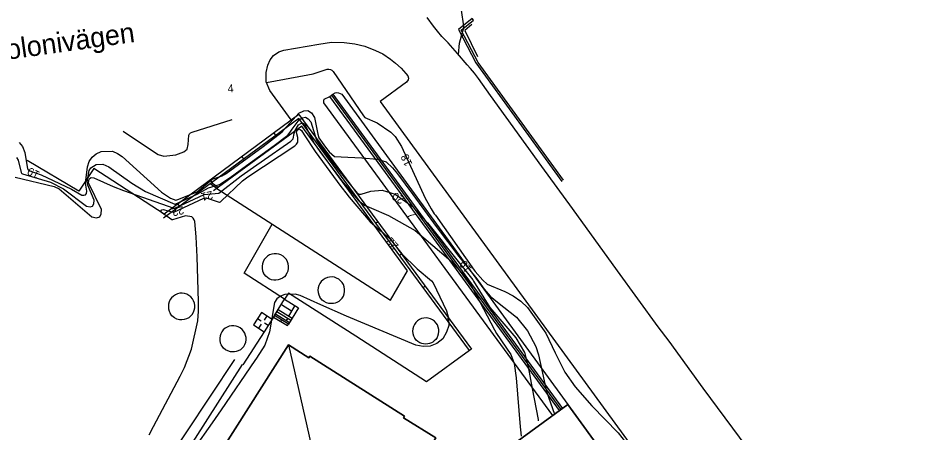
# Model space of a CAD drawing. Extents: x 67169 to 69652, y 20189 to 22818.
# Drawn here: x 69486.1 to 69599.6, y 21189.9 to 21241.7 of the extents above; entities that cross this region are included whole.
import ezdxf

# ---------------------------------------------------------------- set-up
doc = ezdxf.new("R2010")
doc.units = 0
for name, color, linetype in [('BYGGNAD_HUSLIV', 7, 'Continuous'), ('BYGGNAD_HUSLIV 11', 7, 'Continuous'), ('BYGGNADSDETALJER', 7, 'Continuous'), ('BYGGNADSDETALJER 19', 7, 'Continuous'), ('BYGGNADSSYMBOLER', 7, 'Continuous'), ('BYGGNADSSYMBOLER 30', 7, 'Continuous'), ('GATUNAMN', 7, 'Continuous'), ('HOJDKURVOR_2014', 7, 'Continuous'), ('HOJDKURVOR_2014 5M', 7, 'Continuous'), ('HOJDKURVOR_TEXTER_2014', 7, 'Continuous'), ('Instruktioner', 7, 'Continuous'), ('MUR_STAKET', 7, 'Continuous'), ('MUR_STAKET_SYMBOL', 7, 'Continuous'), ('Std_Ritningsstämpel', 7, 'Continuous'), ('VAGAR 121', 7, 'Continuous')]:
    doc.layers.add(name, color=color, linetype=linetype)

msp = doc.modelspace()

# ---------------------------------------------------------------- linework, layer by layer
at = {"layer": 'BYGGNAD_HUSLIV'}
for points in [[(69519.9, 21200.89), (69522.45, 21199.27), (69522.57, 21199.47), (69534.4, 21191.97), (69534.28, 21191.77), (69538.28, 21189.24), (69526.74, 21170.81), (69522.74, 21173.34), (69522.62, 21173.14), (69510.68, 21180.69), (69510.8, 21180.88), (69508.25, 21182.5), (69519.9, 21200.89)], [(69544.44, 21185.88), (69554.8, 21193.43), (69589.88, 21145.14), (69579.54, 21137.63), (69577.94, 21140.02), (69577.23, 21139.47), (69548.93, 21157.38), (69548.85, 21158.64), (69544.93, 21161.12), (69543.76, 21160.66), (69534.77, 21166.35), (69545.88, 21183.92), (69544.44, 21185.88)]]:
    msp.add_lwpolyline(points, dxfattribs=at)
at = {"layer": 'BYGGNAD_HUSLIV 11'}
for points in [[(69519.9, 21200.89), (69522.45, 21199.27), (69522.57, 21199.47), (69534.4, 21191.97), (69534.28, 21191.77), (69538.28, 21189.24), (69526.74, 21170.81), (69522.74, 21173.34), (69522.62, 21173.14), (69510.68, 21180.69), (69510.8, 21180.88), (69508.25, 21182.5), (69519.9, 21200.89)], [(69544.44, 21185.88), (69554.8, 21193.43), (69589.88, 21145.14), (69579.54, 21137.63), (69577.94, 21140.02), (69577.23, 21139.47), (69548.93, 21157.38), (69548.85, 21158.64), (69544.93, 21161.12), (69543.76, 21160.66), (69534.77, 21166.35), (69545.88, 21183.92), (69544.44, 21185.88)]]:
    msp.add_lwpolyline(points, dxfattribs=at)
at = {"layer": 'BYGGNADSDETALJER'}
for p, q in [((69520.7, 21205.77), (69519.89, 21204.47)), ((69518.28, 21204.74), (69520.01, 21203.66)), ((69518.45, 21205.03), (69520.2, 21203.97)), ((69518.6, 21205.27), (69520.34, 21204.2)), ((69519.81, 21204.2), (69519.62, 21203.9))]:
    msp.add_line(p, q, dxfattribs=at)
for points in [[(69519.57, 21209.6), (69519.38, 21209.38), (69519.15, 21209.2), (69518.87, 21209.06), (69518.6, 21208.98), (69518.33, 21208.95), (69518.05, 21208.95), (69517.76, 21209.01), (69517.49, 21209.13), (69517.27, 21209.27), (69517.06, 21209.45), (69516.88, 21209.67), (69516.77, 21209.84)], [(69519.4, 21206.58), (69521.16, 21205.49), (69519.88, 21203.46), (69518.16, 21204.55), (69519.4, 21206.58)], [(69526.58, 21206.7), (69526.38, 21206.48), (69526.17, 21206.31), (69525.95, 21206.17), (69525.74, 21206.1), (69525.5, 21206.05), (69525.22, 21206.03), (69524.95, 21206.05), (69524.64, 21206.14), (69524.37, 21206.28), (69524.09, 21206.47), (69523.92, 21206.66), (69523.79, 21206.85)], [(69507.86, 21204.68), (69507.65, 21204.45), (69507.43, 21204.26), (69507.17, 21204.12), (69506.87, 21204.03), (69506.57, 21203.99), (69506.26, 21204.01), (69505.96, 21204.1), (69505.64, 21204.24), (69505.33, 21204.5), (69505.13, 21204.83)], [(69514.31, 21200.68), (69514.11, 21200.45), (69513.88, 21200.25), (69513.62, 21200.12), (69513.37, 21200.03), (69513.14, 21199.99), (69512.87, 21199.99), (69512.63, 21200), (69512.33, 21200.11), (69512.04, 21200.25), (69511.77, 21200.47), (69511.59, 21200.69), (69511.48, 21200.86)], [(69538.47, 21201.8), (69538.3, 21201.56), (69538.11, 21201.37), (69537.93, 21201.23), (69537.75, 21201.13), (69537.5, 21201.04), (69537.29, 21200.99), (69537.03, 21200.96), (69536.77, 21200.99), (69536.54, 21201.03), (69536.29, 21201.14), (69536.06, 21201.28), (69535.85, 21201.45), (69535.67, 21201.69), (69535.64, 21201.76)]]:
    msp.add_lwpolyline(points, dxfattribs=at)
for centre, radius, start, end in [((69518.25, 21210.6), 1.66, 322.7319, 207.3253), ((69525.24, 21207.69), 1.67, 323.7038, 210.1769), ((69506.54, 21205.68), 1.65, 322.6524, 211.0987), ((69537.04, 21202.6), 1.64, 326.5291, 211.2003), ((69512.95, 21201.62), 1.65, 325.0952, 207.2906)]:
    msp.add_arc(centre, radius, start, end, dxfattribs=at)
at = {"layer": 'BYGGNADSDETALJER 19'}
for p, q in [((69520.7, 21205.77), (69519.89, 21204.47)), ((69518.28, 21204.74), (69520.01, 21203.66)), ((69518.45, 21205.03), (69520.2, 21203.97)), ((69518.6, 21205.27), (69520.34, 21204.2)), ((69519.81, 21204.2), (69519.62, 21203.9))]:
    msp.add_line(p, q, dxfattribs=at)
msp.add_lwpolyline([(69519.4, 21206.58), (69521.16, 21205.49), (69519.88, 21203.46), (69518.16, 21204.55), (69519.4, 21206.58)], dxfattribs=at)
at = {"layer": 'BYGGNADSSYMBOLER'}
for p, q in [((69519, 21205.91), (69520.29, 21205.11)), ((69519, 21205.91), (69519, 21205.91)), ((69519.9, 21200.89), (69526.74, 21170.81))]:
    msp.add_line(p, q, dxfattribs=at)
at = {"layer": 'BYGGNADSSYMBOLER 30'}
msp.add_line((69519.9, 21200.89), (69526.74, 21170.81), dxfattribs=at)
at = {"layer": 'HOJDKURVOR_2014'}
for points in [[(69541.11, 21237.16), (69541.26, 21238.58), (69541.51, 21239.48), (69541.77, 21240.35), (69541.78, 21240.66), (69541.76, 21240.96), (69540.92, 21246.69), (69540.42, 21247.96), (69539.42, 21248.89), (69535.93, 21249.75), (69535.23, 21249.95), (69532.59, 21250.8)], [(69517.15, 21233.66), (69522.33, 21234.59), (69522.98, 21234.75), (69524.71, 21235.33), (69524.94, 21235.33), (69525.14, 21235.29), (69525.32, 21235.18), (69525.48, 21235.02), (69529.26, 21229.49), (69529.45, 21229.28), (69530.99, 21228.59), (69532.66, 21227.44), (69533.2, 21226.92), (69534.02, 21225.64), (69536.98, 21219.2), (69537.28, 21218.6), (69537.72, 21217.85), (69538.1, 21217.26), (69538.24, 21217.07), (69543.09, 21210.2), (69543.22, 21210.02), (69544.17, 21208.94), (69544.69, 21208.47), (69546.91, 21207.53), (69547.95, 21206.99), (69548.91, 21206.34), (69549.75, 21205.54), (69552.03, 21202.32), (69553.22, 21199.89), (69554.41, 21197.47), (69555.69, 21195.62), (69557.77, 21193.25), (69561.07, 21189.9), (69563.38, 21186.98)], [(69486.27, 21226.15), (69486.66, 21225.64), (69486.97, 21224.89), (69487.31, 21222.88), (69487.37, 21222.79), (69487.59, 21222.6), (69488.98, 21222.1), (69492.77, 21220.34), (69494.06, 21219.59), (69494.33, 21219.56), (69494.54, 21219.61), (69494.66, 21219.8), (69494.71, 21220.07), (69494.53, 21221.06), (69494.78, 21223.12), (69495.01, 21223.78), (69495.35, 21224.34), (69495.87, 21224.74), (69496.5, 21225.04), (69497.9, 21225.05), (69498.53, 21224.79), (69499.13, 21224.39), (69504.03, 21219.94), (69505.17, 21219.2), (69505.81, 21218.93), (69506.18, 21219.07), (69506.69, 21219.27), (69508.5, 21219.99), (69510.37, 21221.58), (69511.61, 21221.97), (69511.92, 21222.16), (69512.01, 21222.23), (69512.11, 21222.3), (69516.71, 21225.67), (69519.09, 21227.47), (69519.35, 21227.78), (69521.18, 21229.83), (69521.79, 21230.12), (69522.33, 21230.17), (69522.77, 21229.85), (69523.14, 21229.29), (69523.55, 21227.18), (69523.69, 21226.74), (69524.53, 21225.55), (69524.98, 21224.98), (69525.63, 21224.41), (69527.32, 21224.33), (69529.05, 21224.25), (69531.03, 21224.05), (69532.08, 21223.72), (69532.9, 21223), (69533.49, 21222.22), (69535.41, 21219.65), (69538.36, 21215.64), (69541.19, 21211.92), (69543.4, 21209.14), (69544.32, 21207.85), (69545.09, 21206.95), (69546.01, 21206.2), (69548.38, 21204.34), (69549.75, 21202.61), (69550.78, 21200.66), (69551.14, 21199.62), (69552.13, 21195.04), (69553.12, 21192.2)], [(69485.76, 21221.81), (69490.61, 21220.67), (69491.24, 21220.37), (69495.34, 21216.87), (69495.9, 21216.76), (69496.31, 21216.85), (69496.5, 21217.23), (69496.54, 21217.8), (69494.92, 21221.13), (69494.92, 21221.14), (69495, 21221.56), (69495.05, 21221.65), (69495.24, 21221.76), (69495.59, 21221.75), (69497.98, 21220.65), (69499.28, 21220.16), (69505.58, 21217.93), (69505.68, 21217.94), (69509.35, 21219.66), (69511.19, 21219.81), (69514, 21222), (69515.93, 21223.37), (69516.47, 21223.75), (69520.19, 21226.32), (69520.46, 21226.63), (69520.59, 21227.26), (69520.71, 21227.65), (69521.15, 21228.34), (69521.42, 21228.51), (69521.67, 21228.58), (69521.91, 21228.46), (69523.14, 21225.99), (69523.8, 21225.02), (69526.5, 21221.42), (69528.59, 21218.94), (69529.37, 21218.34), (69530.26, 21217.94), (69532.39, 21217.05), (69535.72, 21215.14), (69536.81, 21214.23), (69539.87, 21211.61), (69540.93, 21210.54), (69542.41, 21208.84), (69542.45, 21208.79), (69545.64, 21202.73), (69545.88, 21202.29), (69547.65, 21199.69), (69548.1, 21198.54), (69548.34, 21196.77), (69548.84, 21190.63), (69548.88, 21190.24), (69548.95, 21189.47)], [(69499.23, 21227.55), (69500.05, 21227.04), (69503.62, 21224.64), (69504.33, 21224.43), (69505.83, 21224.61), (69506.84, 21225), (69507.23, 21225.31), (69507.37, 21225.9), (69507.44, 21227.05), (69507.53, 21227.22), (69507.67, 21227.35), (69507.86, 21227.45), (69512.84, 21229.02)], [(69502.47, 21189.64), (69503.03, 21190.68), (69506.37, 21196.96), (69506.91, 21198.05), (69507.79, 21200.32), (69508.58, 21203.88), (69508.66, 21205.09), (69508.67, 21206.3), (69508.49, 21211.89), (69508.36, 21214.37), (69508.19, 21216.27), (69508.11, 21216.51), (69508, 21216.71), (69507.81, 21216.86), (69507.02, 21217), (69505.41, 21216.49), (69505.33, 21216.48), (69504.05, 21217.4), (69503.98, 21217.56), (69503.98, 21217.68), (69504.07, 21217.75), (69504.24, 21217.79), (69505.5, 21217.43), (69505.57, 21217.44), (69509.33, 21219.19), (69509.56, 21219.25), (69509.62, 21219.25), (69511.23, 21218.71), (69511.27, 21218.71), (69511.4, 21218.75), (69511.43, 21218.77), (69514.15, 21221.38), (69514.66, 21221.74), (69514.83, 21221.86), (69520.7, 21225.73), (69520.91, 21225.95), (69521.05, 21226.19), (69521.06, 21226.77), (69520.89, 21227.42)], [(69520.89, 21227.42), (69520.94, 21227.55), (69521.05, 21227.72), (69521.25, 21227.82), (69521.35, 21227.79), (69521.5, 21227.65), (69521.87, 21227.1), (69523.22, 21225.04), (69526.44, 21220.66), (69526.59, 21220.46), (69527.05, 21219.87), (69527.48, 21219.34), (69530.08, 21216.25), (69531.51, 21215.02), (69532.61, 21214.08), (69534.06, 21212.26), (69535.95, 21210.39), (69537.75, 21208.87), (69537.96, 21208.63), (69539.64, 21205.13), (69539.89, 21204.2), (69539.93, 21203.3), (69539.65, 21202.45), (69539.16, 21201.62), (69538.41, 21201.05), (69537.6, 21200.69), (69536.73, 21200.66), (69535.8, 21200.84), (69527.15, 21204.44), (69523.94, 21205.87), (69521.37, 21207.05), (69520.74, 21207.2), (69519.45, 21207.16), (69518.9, 21206.94), (69518.45, 21206.62), (69518.15, 21206.15), (69517.52, 21202.52), (69516.92, 21200.83), (69515.91, 21199.21), (69515.69, 21198.9), (69511.5, 21192.77), (69510.38, 21191.13), (69508.08, 21187.9)]]:
    msp.add_lwpolyline(points, dxfattribs=at)
at = {"layer": 'HOJDKURVOR_2014 5M'}
msp.add_lwpolyline([(69485.9, 21224.26), (69486.14, 21223.95), (69486.49, 21222.42), (69486.56, 21222.32), (69486.6, 21222.28), (69486.65, 21222.24), (69490.15, 21221.21), (69491.81, 21220.36), (69494.67, 21218.19), (69495.11, 21218.12), (69495.43, 21218.2), (69495.59, 21218.49), (69495.62, 21218.93), (69494.82, 21220.82), (69494.74, 21221.24), (69495, 21222.67), (69495.2, 21222.99), (69495.87, 21223.4), (69496.7, 21223.43), (69497.46, 21223.11), (69500.34, 21221.07), (69502.03, 21220.02), (69505.7, 21218.43), (69505.75, 21218.43), (69508.5, 21219.71), (69509.91, 21220.5), (69511.27, 21220.89), (69512.6, 21221.79), (69514.63, 21223.26), (69518.12, 21225.78), (69519.83, 21227.06), (69520.09, 21227.43), (69520.35, 21227.81), (69521.22, 21229), (69521.64, 21229.25), (69522.03, 21229.32), (69522.36, 21229.12), (69522.67, 21228.73), (69523.39, 21226.45), (69524.21, 21225.23), (69526.13, 21222.7), (69528.46, 21219.82), (69528.71, 21219.7), (69528.98, 21219.71), (69530.16, 21220.07), (69531.6, 21220.21), (69533.22, 21219.68), (69535.37, 21218.14), (69537.25, 21216.12), (69539.08, 21213.82), (69539.44, 21213.36), (69542.9, 21208.99), (69542.92, 21208.98), (69543.01, 21208.85), (69545.05, 21205.53), (69548.29, 21201.74), (69549.36, 21199.9), (69549.82, 21198.14), (69550.32, 21195.41), (69551.06, 21191.53), (69551.09, 21191.39)], dxfattribs=at)
at = {"layer": 'MUR_STAKET'}
for p, q in [((69541.8, 21239.56), (69541.56, 21239.44)), ((69525.25, 21232.05), (69553.92, 21192.79)), ((69521.17, 21229.17), (69504.3, 21216.68)), ((69522.15, 21228.33), (69521.92, 21228.15)), ((69518.06, 21227.36), (69518.28, 21227.04)), ((69514.06, 21224.39), (69514.28, 21224.07)), ((69525.11, 21224.32), (69524.87, 21224.14)), ((69510.1, 21221.45), (69510.33, 21221.14)), ((69510.94, 21220.4), (69510.1, 21220.97)), ((69511.13, 21220.54), (69510.29, 21221.12)), ((69506.06, 21218.46), (69506.28, 21218.15)), ((69531.06, 21216.23), (69530.81, 21216.05)), ((69534.02, 21212.21), (69533.77, 21212.03)), ((69536.97, 21208.2), (69536.72, 21208.01)), ((69518.16, 21204.55), (69516.86, 21202.51)), ((69517.18, 21204.49), (69516.87, 21203.97)), ((69516.01, 21204.15), (69516.48, 21203.86)), ((69516.19, 21202.95), (69516.52, 21203.44)), ((69517.37, 21203.31), (69516.91, 21203.59)), ((69519.01, 21204.01), (69518.89, 21203.82)), ((69539.92, 21204.2), (69539.67, 21204)), ((69516.86, 21202.51), (69514.21, 21198.37))]:
    msp.add_line(p, q, dxfattribs=at)
for points in [[(69554.23, 21221.43), (69543.57, 21236.16), (69541.48, 21240.19), (69543, 21241.43), (69542.82, 21241.66), (69541.14, 21240.26), (69543.28, 21236.09), (69554.03, 21221.3)], [(69542.81, 21240.91), (69541.93, 21240.13), (69543.52, 21236.91)], [(69553.74, 21192.66), (69539.28, 21212.45), (69525.05, 21231.91), (69525.44, 21232.18), (69554.11, 21192.92)], [(69521.17, 21229.66), (69504.35, 21217.19), (69495.57, 21222.91), (69493.69, 21220.09), (69487.26, 21223.92)], [(69521.17, 21229.66), (69542.75, 21200.35), (69542.49, 21200.16), (69521.17, 21229.17)], [(69510.94, 21220.4), (69532.65, 21206.45), (69534.76, 21210.12), (69521.56, 21228.21), (69510.53, 21220.1)], [(69542.49, 21200.16), (69537.14, 21196.25), (69528.31, 21201.94), (69519.89, 21207.34)], [(69517.85, 21204.06), (69516.51, 21204.92), (69515.51, 21203.38), (69516.87, 21202.52)], [(69518.03, 21204.35), (69519.77, 21203.28), (69519.88, 21203.46), (69518.16, 21204.55)], [(69513.14, 21199.04), (69504.04, 21185.31), (69500.27, 21187.64), (69497.6, 21183.51), (69501.41, 21181.2), (69496.57, 21173.57), (69497.8, 21172.78), (69497.8, 21172.78), (69514.15, 21198.4)]]:
    msp.add_lwpolyline(points, dxfattribs=at)
at = {"layer": 'MUR_STAKET_SYMBOL'}
for p, q in [((69542.64, 21238.69), (69542.64, 21238.69)), ((69527.33, 21229.21), (69527.33, 21229.21)), ((69539.37, 21212.72), (69539.37, 21212.72)), ((69520.68, 21206.82), (69520.68, 21206.82)), ((69521.95, 21206.01), (69521.95, 21206.01)), ((69523.2, 21205.21), (69523.2, 21205.21)), ((69524.47, 21204.4), (69524.47, 21204.4)), ((69525.77, 21203.57), (69525.77, 21203.57)), ((69527.04, 21202.75), (69527.04, 21202.75)), ((69528.29, 21201.95), (69528.29, 21201.95)), ((69516.32, 21201.67), (69516.32, 21201.67)), ((69529.51, 21201.16), (69529.51, 21201.16)), ((69515.56, 21200.47), (69515.56, 21200.47)), ((69530.77, 21200.35), (69530.77, 21200.35)), ((69514.68, 21199.11), (69514.68, 21199.11)), ((69532, 21199.56), (69532, 21199.56)), ((69533.32, 21198.71), (69533.32, 21198.71)), ((69541.39, 21199.36), (69541.39, 21199.36)), ((69549.57, 21198.75), (69549.57, 21198.75)), ((69512.41, 21197.92), (69512.41, 21197.92)), ((69513.82, 21197.88), (69513.82, 21197.88)), ((69534.56, 21197.91), (69534.56, 21197.91)), ((69538.92, 21197.55), (69538.92, 21197.55)), ((69540.14, 21198.44), (69540.14, 21198.44)), ((69511.57, 21196.65), (69511.57, 21196.65)), ((69512.99, 21196.59), (69512.99, 21196.59)), ((69535.83, 21197.09), (69535.83, 21197.09)), ((69537.71, 21196.67), (69537.71, 21196.67)), ((69510.78, 21195.46), (69510.78, 21195.46)), ((69512.23, 21195.39), (69512.23, 21195.39)), ((69509.96, 21194.23), (69509.96, 21194.23)), ((69511.43, 21194.14), (69511.43, 21194.14)), ((69509.15, 21193), (69509.15, 21193)), ((69510.63, 21192.89), (69510.63, 21192.89)), ((69508.33, 21191.78), (69508.33, 21191.78)), ((69509.84, 21191.64), (69509.84, 21191.64)), ((69507.47, 21190.48), (69507.47, 21190.48)), ((69509.03, 21190.38), (69509.03, 21190.38))]:
    msp.add_line(p, q, dxfattribs=at)
at = {"layer": 'Std_Ritningsstämpel'}
for points in [[(69519.9, 21200.89), (69508.25, 21182.5), (69510.8, 21180.88), (69510.68, 21180.69), (69522.62, 21173.14), (69522.74, 21173.34), (69526.74, 21170.81), (69538.28, 21189.24), (69534.28, 21191.77), (69534.4, 21191.97), (69522.57, 21199.47), (69522.45, 21199.27)], [(69544.44, 21185.88), (69545.88, 21183.92), (69534.77, 21166.35), (69543.76, 21160.66), (69544.93, 21161.12), (69548.85, 21158.64), (69548.93, 21157.38), (69577.23, 21139.47), (69577.94, 21140.02), (69579.54, 21137.63), (69589.88, 21145.14), (69554.8, 21193.43)]]:
    msp.add_lwpolyline(points, close=True, dxfattribs=at)
at = {"layer": 'VAGAR 121'}
msp.add_line((69526.57, 21232.19), (69554.8, 21193.43), dxfattribs=at)
for points in [[(69577.19, 21188.04), (69571.7, 21195.48), (69567.43, 21201.32), (69566.06, 21203.14), (69561.01, 21210.14), (69555.36, 21217.92), (69551.55, 21223.17), (69545.12, 21232.04), (69543.63, 21234.15), (69543.13, 21234.8), (69542.62, 21235.39), (69542.22, 21235.87), (69541.01, 21237.28), (69539.82, 21238.6), (69539.05, 21239.41), (69538.51, 21240.05), (69538.02, 21240.68), (69537.23, 21241.75)], [(69520.24, 21228.97), (69517.55, 21232.65), (69517.12, 21233.73), (69517.09, 21234.88), (69517.32, 21235.82), (69517.61, 21236.48), (69518.03, 21237), (69518.69, 21237.49), (69519.31, 21237.69), (69523.69, 21238.45), (69525.26, 21238.68), (69526.83, 21238.65), (69528.18, 21238.48), (69529.42, 21238.19), (69530.76, 21237.63), (69531.68, 21237.21), (69532.63, 21236.56), (69533.28, 21236.07), (69533.97, 21235.45), (69534.53, 21234.79), (69534.82, 21234.46), (69534.89, 21234.2), (69534.85, 21233.97), (69534.63, 21233.71), (69531.34, 21231.27), (69599.63, 21137.67)], [(69552.91, 21192.05), (69524.32, 21231.11), (69524.29, 21231.34), (69524.37, 21231.55), (69525.05, 21231.91)], [(69525.44, 21232.18), (69525.71, 21232.37), (69525.88, 21232.41), (69526.16, 21232.35), (69526.57, 21232.19)], [(69519.89, 21207.34), (69519.4, 21206.58), (69514.37, 21209.85), (69517.86, 21215.96)]]:
    msp.add_lwpolyline(points, dxfattribs=at)

# ---------------------------------------------------------------- texts
at = {"layer": 'GATUNAMN'}
msp.add_text('Kolonivägen', height=2.5, rotation=7.9373, dxfattribs=at).set_placement((69482.58, 21236.18))
at = {"layer": 'HOJDKURVOR_TEXTER_2014'}
for s, rotation, p in [('18', 114.6757, (69535.39, 21223.47)), ('19', 152.9606, (69488.91, 21222.43)), ('21', 192.3638, (69510.33, 21220.12)), ('20', 149.8668, (69534.48, 21219.25)), ('22', 192.8888, (69506.71, 21218.22)), ('22', 131.7141, (69533.71, 21213.29)), ('19', 128.3994, (69542.84, 21210.39))]:
    msp.add_text(s, height=1, rotation=rotation, dxfattribs=at).set_placement(p)
at = {"layer": 'Instruktioner'}
for s, rotation, p in [('4', 3.5046, (69512.32, 21232.38)), ('7', 306.6194, (69534.65, 21217.11))]:
    msp.add_text(s, height=1, rotation=rotation, dxfattribs=at).set_placement(p)

doc.saveas('drawing.dxf')
